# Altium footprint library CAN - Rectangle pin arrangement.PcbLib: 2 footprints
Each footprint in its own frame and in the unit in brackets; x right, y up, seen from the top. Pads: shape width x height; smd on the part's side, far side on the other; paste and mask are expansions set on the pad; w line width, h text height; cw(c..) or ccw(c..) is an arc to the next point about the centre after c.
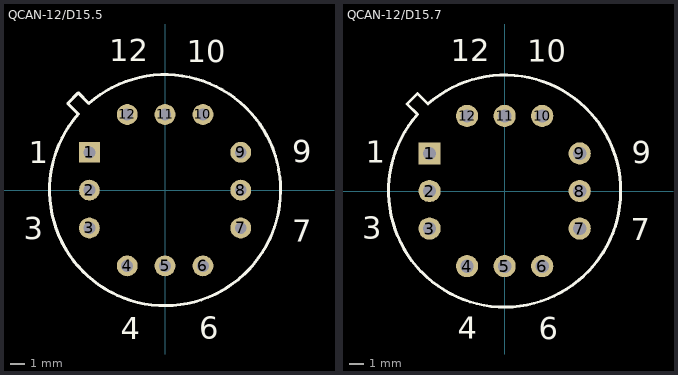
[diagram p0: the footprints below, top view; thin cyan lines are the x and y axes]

## QCAN-12/D15.5 [mm]
pads (12):
  rect 1.4x1.4 hole 0.8: 1(-5.08,2.54)
  round 1.4 hole 0.8: 2(-5.08,0) 3(-5.08,-2.54) 4(-2.54,-5.08) 5(0,-5.08) 6(2.54,-5.08) 7(5.08,-2.54) 8(5.08,0) 9(5.08,2.54) 10(2.54,5.08) 11(0,5.08) 12(-2.54,5.08)
Top Overlay:
  lines w0.2: -6.529,5.822 -5.822,5.115 ccw(c0,0) -5.115,5.822 -5.822,6.529 -6.529,5.822
  text "12" at -3.754,8.642 h1.5
  text "10" at 1.446,8.583 h1.5
  text "9" at 8.519,1.867 h1.5
  text "7" at 8.519,-3.453 h1.5
  text "6" at 2.278,-9.96 h1.5
  text "4" at -2.982,-9.99 h1.5
  text "3" at -9.49,-3.304 h1.5
  text "1" at -9.16,1.808 h1.5

## QCAN-12/D15.7 [mm]
pads (12):
  rect 1.5x1.5 hole 0.9: 1(-5.08,2.54)
  round 1.5 hole 0.9: 2(-5.08,0) 3(-5.08,-2.54) 4(-2.54,-5.08) 5(0,-5.08) 6(2.54,-5.08) 7(5.08,-2.54) 8(5.08,0) 9(5.08,2.54) 10(2.54,5.08) 11(0,5.08) 12(-2.54,5.08)
Top Overlay:
  lines w0.2: -6.6,5.893 -5.893,6.6 -5.186,5.893 cw(c0,0) -5.893,5.186 -6.6,5.893
  text "1" at -9.398,1.916 h1.5
  text "3" at -9.639,-3.231 h1.5
  text "4" at -3.169,-9.979 h1.5
  text "6" at 2.298,-10.009 h1.5
  text "7" at 8.534,-3.321 h1.5
  text "9" at 8.594,1.886 h1.5
  text "10" at 1.525,8.76 h1.5
  text "12" at -3.64,8.782 h1.5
